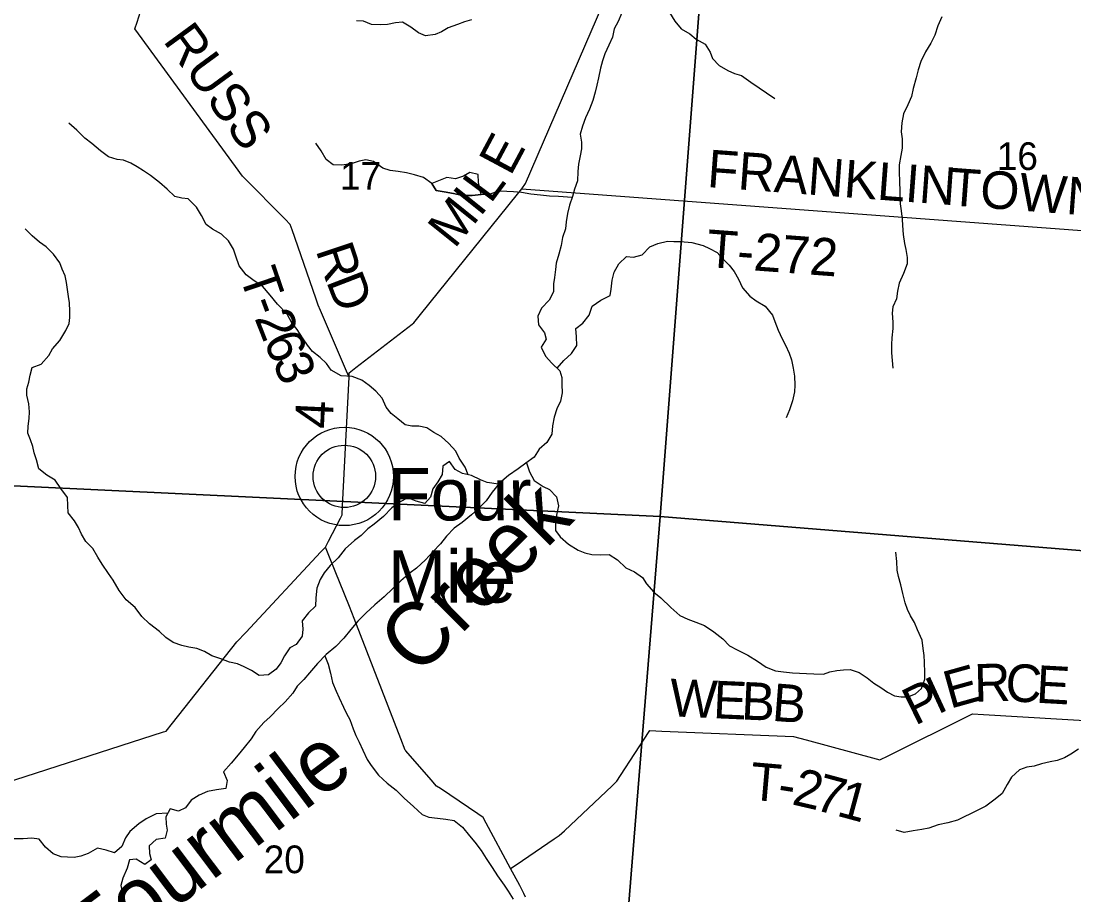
# Model space of a CAD drawing. Extents: x 0 to 34, y 0 to 22.
# Drawn here: x 27.233 to 28.825, y 16.193 to 17.514 of the extents above; entities that cross this region are included whole.
import ezdxf

# ---------------------------------------------------------------- set-up
doc = ezdxf.new("R2010")
doc.units = 0
for name, color, linetype in [('GM_X_Corporation', 7, 'Continuous'), ('GM_X_County_Road', 7, 'Continuous'), ('GM_X_County_Road_Text', 7, 'Continuous'), ('GM_X_Minor_Lake', 7, 'Continuous'), ('GM_X_Minor_River', 7, 'Continuous'), ('GM_X_Minor_River_Text', 7, 'Continuous'), ('GM_X_Section_Text', 7, 'Continuous'), ('GM_X_Township_Road', 7, 'Continuous'), ('GM_X_Township_Road_Text', 7, 'Continuous'), ('GM_X_Unincorporated', 7, 'Continuous'), ('GM_X_Unincorporated_Location', 7, 'Continuous'), ('GM_X_Unincorporated_Text', 7, 'Continuous')]:
    doc.layers.add(name, color=color, linetype=linetype)

msp = doc.modelspace()

# ---------------------------------------------------------------- linework, layer by layer
at = {"layer": 'GM_X_Corporation'}
for points in [[(27.1442, 17.8319), (27.2101, 17.8272), (28.2146, 17.7472), (28.2741, 17.7417), (28.199, 16.7653), (27.1145, 16.8163), (27.1132, 17.3107)], [(28.2741, 17.7417), (29.263, 17.6631), (29.176, 16.6858), (28.199, 16.7653)], [(27.1145, 16.8163), (28.199, 16.7653), (28.1104, 15.671), (27.112, 15.7689)], [(29.176, 16.6858), (29.0551, 15.5941), (28.1104, 15.671), (28.199, 16.7653)]]:
    msp.add_lwpolyline(points, close=True, dxfattribs=at)
at = {"layer": 'GM_X_County_Road'}
for points in [[(27.6929, 16.7189), (27.6976, 16.7278), (27.7156, 16.7624), (27.7183, 16.7675), (27.719, 16.7812), (27.7286, 16.9759), (27.7289, 16.9825), (27.7391, 16.9903), (27.824, 17.0558), (27.8264, 17.0577), (27.8367, 17.0705), (27.9836, 17.2526), (27.9899, 17.2605), (27.9956, 17.2684), (28.2389, 17.8323)], [(26.7705, 16.2651), (26.7841, 16.2703), (26.8132, 16.281), (26.8372, 16.2896), (26.8937, 16.313), (26.9141, 16.3129), (27.0708, 16.3069), (27.0742, 16.3068), (27.0874, 16.3161), (27.1034, 16.3274), (27.1064, 16.3295), (27.1215, 16.3344), (27.1588, 16.3464), (27.448, 16.4395), (27.452, 16.4408), (27.4615, 16.4528), (27.5592, 16.5754), (27.5725, 16.5898), (27.6861, 16.7116), (27.6929, 16.7189)], [(27.9953, 16.1896), (27.993, 16.1954), (27.9867, 16.2071), (27.9729, 16.2329), (27.9361, 16.3016), (27.9315, 16.3101), (27.9234, 16.3156), (27.8668, 16.3537), (27.861, 16.3576), (27.8528, 16.367), (27.8143, 16.4111), (27.8135, 16.4119), (27.8069, 16.429), (27.7366, 16.6108), (27.7293, 16.6289), (27.7001, 16.7011), (27.6929, 16.7189)]]:
    msp.add_lwpolyline(points, dxfattribs=at)
at = {"layer": 'GM_X_Minor_Lake'}
for points in [[(27.9283, 17.2518), (27.9242, 17.27), (27.9239, 17.2821), (27.9114, 17.2852), (27.9015, 17.2795), (27.8894, 17.2754), (27.8766, 17.2774), (27.8538, 17.2687)], [(27.8538, 17.2687), (27.8606, 17.2577), (27.8727, 17.2558), (27.8867, 17.2534), (27.9003, 17.2504), (27.9147, 17.2503), (27.9283, 17.2518)]]:
    msp.add_lwpolyline(points, dxfattribs=at)
at = {"layer": 'GM_X_Minor_River'}
for points in [[(28.213, 17.527), (28.2213, 17.5137), (28.2307, 17.5023), (28.2439, 17.4947), (28.2537, 17.4867), (28.267, 17.479), (28.2745, 17.4669), (28.2782, 17.4574), (28.2884, 17.4467), (28.3016, 17.4391), (28.3114, 17.4349), (28.322, 17.4318), (28.336, 17.4215), (28.3722, 17.3971)], [(27.9138, 17.516), (27.9031, 17.5127), (27.8925, 17.5089), (27.8785, 17.5037), (27.8683, 17.498), (27.8588, 17.4935), (27.8444, 17.4917), (27.8339, 17.4962), (27.8222, 17.5046), (27.8097, 17.5126), (27.7987, 17.5115), (27.7866, 17.5089), (27.776, 17.5082), (27.7628, 17.509), (27.7503, 17.514), (27.7401, 17.5144)], [(28.1412, 17.5265), (28.1354, 17.5133), (28.1293, 17.5023), (28.127, 17.4898), (28.1213, 17.4777), (28.1152, 17.4645), (28.1118, 17.4539), (28.1087, 17.4429), (28.1056, 17.4281), (28.1033, 17.4171), (28.1006, 17.4065), (28.0972, 17.394), (28.0922, 17.3808), (28.0861, 17.3675), (28.0815, 17.3554), (28.0781, 17.3433), (28.0803, 17.3308), (28.0802, 17.3209), (28.0783, 17.3103), (28.0756, 17.2978), (28.0748, 17.2865), (28.074, 17.2724), (28.0694, 17.2599), (28.0664, 17.2486), (28.0618, 17.2357), (28.0587, 17.2232), (28.0571, 17.2103), (28.056, 17.1997), (28.0514, 17.1868), (28.0494, 17.1747), (28.0456, 17.1618), (28.0418, 17.1478), (28.0406, 17.1384), (28.0394, 17.1266), (28.0379, 17.1168), (28.0378, 17.1046), (28.0314, 17.0922), (28.0196, 17.0801), (28.0139, 17.068), (28.0153, 17.0547), (28.024, 17.0429), (28.0266, 17.0334), (28.019, 17.0209), (28.0257, 17.0076), (28.0355, 16.997), (28.0472, 16.9852), (28.0502, 16.9753), (28.0506, 16.9647), (28.0509, 16.9518), (28.0482, 16.9393), (28.0428, 16.928), (28.0386, 16.9155), (28.0363, 16.9022), (28.0351, 16.8897), (28.0279, 16.8769), (28.0161, 16.867), (28.0085, 16.8546), (27.996, 16.8455), (27.9846, 16.8372)], [(28.625, 17.5205), (28.6189, 17.5069), (28.6143, 17.4925), (28.6082, 17.4804), (28.6002, 17.4675), (28.593, 17.4531), (28.5891, 17.4403), (28.5861, 17.4282), (28.5815, 17.4119), (28.5788, 17.4001), (28.5734, 17.3876), (28.5669, 17.374), (28.5642, 17.36), (28.5634, 17.3464), (28.5649, 17.3361), (28.5648, 17.3217), (28.5629, 17.3107), (28.5602, 17.2967), (28.5606, 17.2861), (28.5609, 17.2709), (28.5616, 17.2573), (28.5612, 17.2471), (28.5619, 17.2376), (28.5634, 17.227), (28.5648, 17.2144), (28.5656, 17.205), (28.5663, 17.1913), (28.5685, 17.178), (28.5707, 17.1686), (28.5726, 17.1564), (28.5725, 17.1469), (28.5668, 17.1322), (28.5603, 17.1178), (28.558, 17.1057), (28.5564, 17.0939), (28.5507, 17.0822), (28.5499, 17.0727), (28.5506, 17.0587), (28.5506, 17.0492), (28.5494, 17.0352), (28.5486, 17.025), (28.549, 17.0125), (28.5497, 17.0011), (28.5508, 16.9893)], [(27.9086, 16.8282), (27.9044, 16.8398), (27.8954, 16.8535), (27.8902, 16.8637), (27.8796, 16.8755), (27.8679, 16.8858), (27.857, 16.8923), (27.8464, 16.8992), (27.8343, 16.9015), (27.8237, 16.9015), (27.8135, 16.9035), (27.8022, 16.9126), (27.7924, 16.9206), (27.7849, 16.9305), (27.7785, 16.9438), (27.7691, 16.9548), (27.7593, 16.9632), (27.7479, 16.9712), (27.7332, 16.9765), (27.7169, 16.9777), (27.7018, 16.9865), (27.6947, 16.9964), (27.6849, 17.0055), (27.6732, 17.0143), (27.666, 17.0242), (27.6585, 17.0352), (27.6502, 17.0477), (27.6423, 17.058), (27.6352, 17.0709), (27.6205, 17.0861), (27.6092, 17.0995), (27.5979, 17.1132), (27.5854, 17.1212), (27.573, 17.1303), (27.5624, 17.144), (27.5576, 17.1584), (27.5542, 17.1694), (27.5463, 17.182), (27.5358, 17.1919), (27.5222, 17.1995), (27.5124, 17.2064), (27.5056, 17.22), (27.4981, 17.2329), (27.4856, 17.2451), (27.4758, 17.2463), (27.4652, 17.2486), (27.4535, 17.26), (27.4422, 17.2699), (27.4287, 17.2806), (27.4181, 17.2875), (27.4083, 17.2936), (27.3985, 17.2993), (27.3879, 17.3039), (27.3781, 17.3047), (27.3652, 17.3089), (27.3531, 17.318), (27.3396, 17.3287), (27.329, 17.3371), (27.3169, 17.3489), (27.3049, 17.3599)], [(28.0658, 17.2472), (28.0452, 17.2487), (28.0316, 17.2495), (28.0183, 17.251), (28.0036, 17.2526), (27.9896, 17.2549), (27.9771, 17.2557), (27.9673, 17.2562), (27.954, 17.257), (27.9404, 17.2517), (27.9283, 17.2518), (27.9147, 17.2503), (27.9003, 17.2504), (27.8867, 17.2534), (27.8727, 17.2558), (27.8606, 17.2577), (27.8538, 17.2687), (27.8414, 17.2775), (27.8274, 17.2817), (27.8153, 17.2848), (27.8028, 17.2867), (27.7907, 17.2879), (27.7798, 17.2918), (27.7654, 17.3017), (27.7541, 17.3044), (27.7442, 17.3021), (27.7317, 17.2984), (27.7177, 17.2962), (27.7049, 17.2966), (27.6939, 17.305), (27.6864, 17.3179), (27.6785, 17.3293)], [(27.2995, 17.1287), (27.295, 17.139), (27.2912, 17.1488), (27.2818, 17.1617), (27.2705, 17.1728), (27.2607, 17.1796), (27.2494, 17.1895), (27.2392, 17.1998)], [(28.0431, 16.9894), (28.0533, 17.0011), (28.0651, 17.0113), (28.0731, 17.0234), (28.0728, 17.0367), (28.0717, 17.0492), (28.0819, 17.0571), (28.0918, 17.0692), (28.0964, 17.0832), (28.1093, 17.0922), (28.1233, 17.099), (28.1249, 17.1085), (28.1264, 17.1221), (28.1295, 17.1342), (28.1367, 17.1471), (28.1481, 17.158), (28.1587, 17.1569), (28.172, 17.1606), (28.1833, 17.1727), (28.1955, 17.178), (28.2099, 17.1813), (28.2197, 17.1809), (28.2299, 17.1809), (28.2469, 17.1793), (28.2639, 17.175), (28.2738, 17.1701), (28.2851, 17.164), (28.2937, 17.1545), (28.3035, 17.1449), (28.3107, 17.1354), (28.3175, 17.1237), (28.3235, 17.1107), (28.3344, 17.0982), (28.3442, 17.0913), (28.3578, 17.0829), (28.3687, 17.0693), (28.3725, 17.0598), (28.3773, 17.0469), (28.3837, 17.0336), (28.3886, 17.0241), (28.3942, 17.0119), (28.3976, 17.002), (28.4002, 16.9891), (28.402, 16.977), (28.4027, 16.9634), (28.402, 16.9535), (28.3989, 16.9399), (28.3947, 16.9262), (28.3897, 16.9141)], [(27.9546, 16.8138), (27.9373, 16.8166), (27.9274, 16.8204), (27.9139, 16.8269), (27.9002, 16.8303), (27.8889, 16.8361), (27.8803, 16.8482), (27.8704, 16.8414), (27.8696, 16.8286), (27.8631, 16.8176), (27.8551, 16.807), (27.8517, 16.7945), (27.843, 16.7847), (27.8301, 16.7882), (27.8173, 16.7931), (27.8048, 16.7867), (27.7934, 16.7781), (27.7808, 16.7652), (27.7668, 16.7535), (27.7569, 16.7464), (27.7471, 16.7365), (27.7368, 16.7286), (27.7228, 16.7162), (27.7121, 16.7026), (27.7, 16.6909), (27.6912, 16.6799), (27.6852, 16.6701), (27.6802, 16.6568), (27.6786, 16.642), (27.6778, 16.6295), (27.6676, 16.6197), (27.6577, 16.6076), (27.6588, 16.5947), (27.658, 16.5841), (27.6489, 16.5716), (27.639, 16.5668), (27.631, 16.5543), (27.6253, 16.5441), (27.6185, 16.5342), (27.6067, 16.5259), (27.5927, 16.5245), (27.5814, 16.5325), (27.57, 16.5378), (27.5598, 16.5424), (27.5481, 16.5447), (27.5349, 16.5501), (27.5213, 16.5547), (27.51, 16.5612), (27.4983, 16.5654), (27.4862, 16.5677), (27.476, 16.57), (27.4627, 16.5746), (27.4518, 16.5823), (27.442, 16.5914), (27.4269, 16.6028), (27.4156, 16.6139), (27.4051, 16.6275), (27.3915, 16.6393), (27.3813, 16.6534), (27.3719, 16.6686), (27.3648, 16.6789), (27.3554, 16.6929), (27.349, 16.7036), (27.3415, 16.7165), (27.3309, 16.7275), (27.3241, 16.7385), (27.3196, 16.7484), (27.3136, 16.7583), (27.3038, 16.7705), (27.3035, 16.7818), (27.3028, 16.794), (27.293, 16.8073), (27.2843, 16.8202), (27.2715, 16.8278), (27.2598, 16.837), (27.2561, 16.851), (27.2527, 16.8613), (27.2508, 16.8707), (27.2471, 16.881), (27.243, 16.8912), (27.2434, 16.9015), (27.245, 16.9132), (27.2457, 16.9234), (27.2447, 16.9356), (27.2417, 16.9485), (27.2413, 16.9583), (27.2444, 16.9682), (27.2463, 16.9788), (27.2498, 16.9902), (27.263, 16.9954), (27.2748, 17.0086), (27.2805, 17.0185), (27.2912, 17.0313), (27.3007, 17.0461), (27.3056, 17.0567), (27.3064, 17.0661), (27.3065, 17.0756), (27.3058, 17.0881), (27.3043, 17.0976), (27.3013, 17.1188), (27.2995, 17.1287)], [(27.997, 16.8462), (28.0016, 16.8326), (28.0088, 16.8197), (28.022, 16.8102), (28.0318, 16.806), (28.0424, 16.7949), (28.0453, 16.7813), (28.0423, 16.7672), (28.0407, 16.757), (28.041, 16.7441), (28.0478, 16.7346), (28.0603, 16.7232), (28.075, 16.7141), (28.0852, 16.7102), (28.0958, 16.7079), (28.1086, 16.7071), (28.1219, 16.7074), (28.1347, 16.6998), (28.1471, 16.6876), (28.1603, 16.6815), (28.1724, 16.6731), (28.1784, 16.6632), (28.1894, 16.6507), (28.1999, 16.6419), (28.2154, 16.6275), (28.2286, 16.6153), (28.2407, 16.6099), (28.2528, 16.6053), (28.266, 16.6004), (28.2803, 16.5908), (28.2939, 16.5802), (28.3041, 16.5695), (28.3154, 16.5634), (28.3316, 16.5554), (28.346, 16.5466), (28.3592, 16.5375), (28.3735, 16.5317), (28.3856, 16.5301), (28.3993, 16.5286), (28.4098, 16.5282), (28.4201, 16.5277), (28.4314, 16.5273), (28.4462, 16.5269), (28.4556, 16.5303), (28.4662, 16.5321), (28.4761, 16.5332), (28.4863, 16.5339), (28.4999, 16.5293), (28.512, 16.5213), (28.5221, 16.5133), (28.5327, 16.5065), (28.5429, 16.4996), (28.5535, 16.4942), (28.5633, 16.4923), (28.5735, 16.4927), (28.5849, 16.4972), (28.5944, 16.5051), (28.5993, 16.5191), (28.599, 16.5286), (28.5987, 16.5449), (28.5983, 16.5551), (28.5969, 16.5657), (28.595, 16.5779), (28.5883, 16.5938), (28.5834, 16.6048), (28.5777, 16.6147), (28.5732, 16.6246), (28.5695, 16.6348), (28.5661, 16.6489), (28.5628, 16.6618), (28.5594, 16.6743), (28.5576, 16.6841), (28.5569, 16.697), (28.5554, 16.7114)], [(27.9846, 16.8372), (27.9698, 16.827), (27.9562, 16.8157), (27.9452, 16.8017), (27.936, 16.7889), (27.9239, 16.7768), (27.9136, 16.7674), (27.8996, 16.756), (27.8878, 16.7474), (27.8761, 16.7353), (27.8669, 16.7236), (27.8555, 16.7119), (27.8445, 16.6994), (27.8305, 16.6869), (27.821, 16.6798), (27.807, 16.6677), (27.7948, 16.6564), (27.7819, 16.6435), (27.7675, 16.6318), (27.7538, 16.619), (27.742, 16.6069), (27.7314, 16.5944), (27.7208, 16.5812), (27.7086, 16.5688), (27.6942, 16.5567), (27.6809, 16.5427), (27.6691, 16.5287), (27.6604, 16.5189), (27.6501, 16.5087), (27.6437, 16.4981), (27.6323, 16.4849), (27.6216, 16.4747), (27.6095, 16.4622), (27.5996, 16.4539), (27.5878, 16.44), (27.5806, 16.429), (27.5703, 16.4161), (27.5609, 16.4048), (27.5502, 16.392), (27.5388, 16.3791), (27.5444, 16.3662), (27.5425, 16.3537), (27.5281, 16.3519), (27.5149, 16.3496), (27.502, 16.344), (27.4902, 16.3365), (27.4815, 16.3248), (27.4709, 16.3195), (27.4584, 16.3233), (27.4519, 16.3112), (27.4523, 16.3002), (27.4537, 16.2907), (27.4507, 16.2786), (27.4371, 16.2768), (27.4264, 16.267), (27.4271, 16.2556), (27.4294, 16.2461), (27.4199, 16.2389), (27.4067, 16.2473), (27.3968, 16.2462), (27.393, 16.2334), (27.3865, 16.2186), (27.3838, 16.2072), (27.3868, 16.1947), (27.3879, 16.1777)], [(27.6923, 16.5547), (27.6972, 16.5419), (27.7005, 16.5282), (27.7039, 16.5142), (27.7091, 16.5013), (27.7136, 16.491), (27.7204, 16.477), (27.7249, 16.4675), (27.7298, 16.458), (27.735, 16.4439), (27.7391, 16.4341), (27.744, 16.4238), (27.7493, 16.4117), (27.756, 16.398), (27.762, 16.3885), (27.7733, 16.374), (27.7865, 16.3622), (27.7997, 16.3512), (27.8122, 16.3394), (27.8261, 16.3268), (27.8393, 16.3147), (27.8491, 16.3108), (27.8624, 16.3093), (27.8749, 16.3077), (27.8877, 16.3054), (27.9002, 16.2955), (27.9107, 16.2825), (27.919, 16.273), (27.9284, 16.2601), (27.9359, 16.2483), (27.945, 16.2346), (27.9529, 16.2217), (27.9634, 16.208), (27.9694, 16.1985), (27.9769, 16.1864)], [(28.8315, 16.4132), (28.8201, 16.406), (28.8103, 16.4004), (28.7993, 16.3963), (28.7887, 16.394), (28.7754, 16.3911), (28.7645, 16.3877), (28.7535, 16.3862), (28.7421, 16.3821), (28.73, 16.3712), (28.7239, 16.3602), (28.7159, 16.3466)], [(28.7159, 16.3466), (28.7053, 16.3376), (28.6913, 16.3274), (28.6784, 16.3206), (28.6486, 16.3063)], [(27.4547, 16.3165), (27.4372, 16.3158), (27.422, 16.3079), (27.411, 16.3004), (27.3974, 16.2891), (27.3905, 16.2792), (27.3852, 16.266), (27.3738, 16.2566), (27.3613, 16.2608), (27.3485, 16.2635), (27.3341, 16.2556), (27.3231, 16.2518), (27.3132, 16.2496), (27.303, 16.25), (27.2932, 16.2508), (27.2811, 16.255), (27.2698, 16.2653), (27.26, 16.2771), (27.249, 16.2786), (27.2358, 16.2776), (27.2226, 16.2776)], [(28.6486, 16.3063), (28.6341, 16.3021), (28.6193, 16.2988), (28.6053, 16.2939), (28.5947, 16.292), (28.5818, 16.2898), (28.5678, 16.2876), (28.5561, 16.2911)]]:
    msp.add_lwpolyline(points, dxfattribs=at)
at = {"layer": 'GM_X_Township_Road'}
for points in [[(27.7286, 16.9759), (27.7247, 16.985), (27.6854, 17.0764), (27.6819, 17.0846), (27.6783, 17.0949), (27.6426, 17.1984), (27.6398, 17.2066), (27.6319, 17.2145), (27.569, 17.2782), (27.5677, 17.2795), (27.5571, 17.2941), (27.4104, 17.4947), (27.405, 17.5021), (27.4082, 17.5124), (27.4262, 17.5693)], [(27.9899, 17.2605), (29.2296, 17.1682), (29.3169, 17.276)], [(27.9729, 16.2329), (27.9811, 16.2385), (28.0388, 16.2776), (28.0465, 16.2828), (28.0542, 16.2901), (28.1267, 16.3582), (28.1337, 16.3648), (28.1393, 16.3734), (28.1826, 16.4403), (28.1834, 16.4416), (28.2018, 16.4408), (28.4006, 16.4324), (28.4198, 16.4273), (28.5255, 16.3987), (28.5313, 16.3971), (28.5437, 16.4033), (28.6685, 16.4652), (28.6713, 16.4666), (28.688, 16.4656), (29.1549, 16.438)]]:
    msp.add_lwpolyline(points, dxfattribs=at)
at = {"layer": 'GM_X_Unincorporated'}
for radius in [0.0744, 0.0472]:
    msp.add_circle((27.7215, 16.8257), radius, dxfattribs=at)
at = {"layer": 'GM_X_Unincorporated_Location'}
msp.add_line((27.7215, 16.8257), (27.7215, 16.8257), dxfattribs=at)

# ---------------------------------------------------------------- texts
at = {"layer": 'GM_X_County_Road_Text'}
for s, rotation, p in [('E', 61.8704, (27.9728, 17.2784)), ('L', 53.3902, (27.9426, 17.2367)), ('I', 51.3222, (27.9267, 17.2167)), ('M', 51.2885, (27.8881, 17.1686)), ('4', 87.2752, (27.7034, 16.8969))]:
    msp.add_text(s, height=0.0568, rotation=rotation, dxfattribs=at).set_placement(p)
at = {"layer": 'GM_X_Minor_River_Text'}
for s, rotation, p in [('Creek', 45.0029, (27.8325, 16.521)), ('Fourmile', 37.0021, (27.3461, 16.0821))]:
    msp.add_text(s, height=0.0947, rotation=rotation, dxfattribs=at).set_placement(p)
at = {"layer": 'GM_X_Section_Text'}
for s, p in [('16', (28.7079, 17.2889)), ('17', (27.715, 17.259)), ('20', (27.5996, 16.2259))]:
    msp.add_text(s, height=0.04186, rotation=0, dxfattribs=at).set_placement(p)
at = {"layer": 'GM_X_Township_Road_Text'}
for s, height, rotation, p in [('RUSS', 0.05682, 306.2098, (27.4464, 17.4841)), ('FRANKLIN', 0.05682, 355.7789, (28.2691, 17.2632)), ('TOWNHOUSE', 0.05682, 355.732, (28.635, 17.2357)), ('T-272', 0.05682, 355.7742, (28.2677, 17.1425)), ('R', 0.0568, 288.393, (27.6779, 17.1678)), ('T', 0.0568, 288.889, (27.5624, 17.1301)), ('D', 0.0568, 291.0828, (27.6936, 17.1209)), ('-', 0.0568, 290.2911, (27.5767, 17.0885)), ('2', 0.0568, 291.5403, (27.5852, 17.0653)), ('6', 0.0568, 292.7366, (27.5986, 17.0316)), ('3', 0.0568, 293.1368, (27.6123, 16.9989)), ('E', 0.0568, 15.6163, (28.6372, 16.4742)), ('R', 0.0568, 1.495, (28.6745, 16.4851)), ('C', 0.0568, 356.8018, (28.7199, 16.4863)), ('E', 0.0568, 356.7755, (28.7665, 16.4837)), ('W', 0.0568, 357.4787, (28.2126, 16.4632)), ('E', 0.0568, 357.4749, (28.2784, 16.4603)), ('B', 0.0568, 357.4426, (28.3209, 16.4584)), ('B', 0.0568, 355.5501, (28.367, 16.4564)), ('P', 0.0568, 26.2909, (28.5842, 16.4484)), ('I', 0.0568, 24.8019, (28.6182, 16.4652)), ('T', 0.0568, 355.0651, (28.3333, 16.3372)), ('2', 0.0568, 346.9138, (28.3966, 16.3303)), ('7', 0.0568, 344.8759, (28.4302, 16.3225)), ('-', 0.0568, 350.9894, (28.3746, 16.3337)), ('1', 0.0568, 344.8759, (28.464, 16.3133))]:
    msp.add_text(s, height=height, rotation=rotation, dxfattribs=at).set_placement(p)
at = {"layer": 'GM_X_Unincorporated_Text'}
for s, p in [('Four', (27.7875, 16.7592)), ('Mile', (27.7875, 16.635))]:
    msp.add_text(s, height=0.07898, rotation=0, dxfattribs=at).set_placement(p)

doc.saveas('drawing.dxf')
